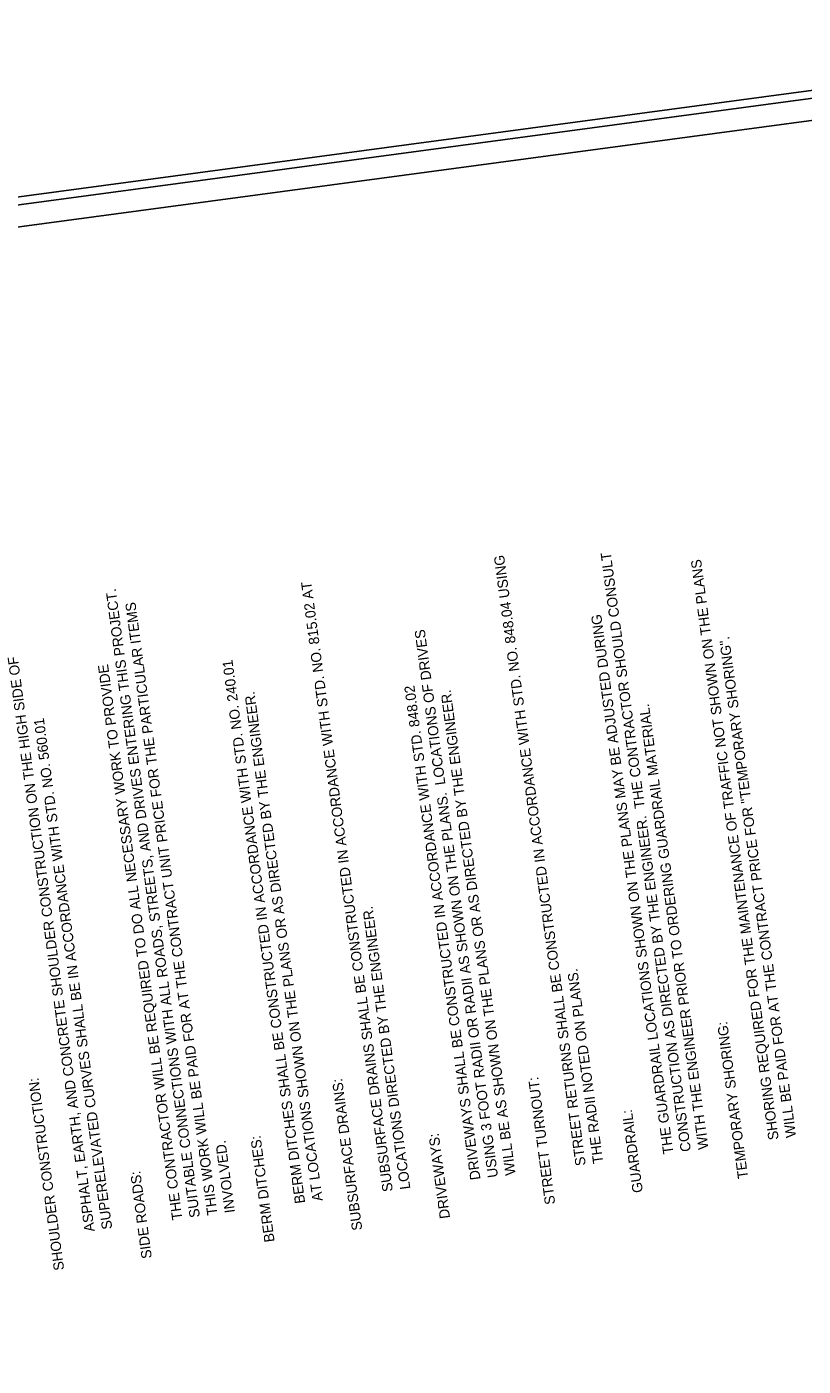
# Model space of a CAD drawing. Extents: x 2573931 to 2578852, y 980053 to 983667.
# Drawn here: x 2574414 to 2574945, y 982228 to 983142 of the extents above; entities that cross this region are included whole.
import ezdxf

# ---------------------------------------------------------------- set-up
doc = ezdxf.new("R2010")
doc.units = 0
for name, color, linetype in [('Sheet Border Standard 30in CELL', 7, 'Continuous'), ('Sheet Data Text CELL', 7, 'Continuous'), ('Sheet Plot Border Inside CELL', 7, 'Continuous'), ('Sheet Plot Border Outside CELL', 7, 'Continuous')]:
    doc.layers.add(name, color=color, linetype=linetype)

msp = doc.modelspace()

# ---------------------------------------------------------------- linework, layer by layer
at = {"layer": 'Sheet Border Standard 30in CELL'}
msp.add_lwpolyline([(2573998.57, 982950.72), (2574237.85, 981166.7), (2575486.67, 981334.19), (2575247.39, 983118.21)], close=True, dxfattribs=at)
at = {"layer": 'Sheet Plot Border Inside CELL'}
msp.add_lwpolyline([(2573993.55, 982965.18), (2574259.38, 980983.13), (2575514.27, 981151.44), (2575248.43, 983133.49)], close=True, dxfattribs=at)
at = {"layer": 'Sheet Plot Border Outside CELL'}
msp.add_lwpolyline([(2573966.13, 982966.95), (2574234.76, 980964.09), (2575543.04, 981139.56), (2575274.41, 983142.42)], close=True, dxfattribs=at)

# ---------------------------------------------------------------- texts
at = {"layer": 'Sheet Data Text CELL'}
for s, p in [('         STREET RETURNS SHALL BE CONSTRUCTED IN ACCORDANCE WITH STD. NO. 848.04 USING ', (2574799.57, 982341.9)), ('         CONSTRUCTION AS DIRECTED BY THE ENGINEER.  THE CONTRACTOR SHOULD CONSULT', (2574871.47, 982351.54)), ('         SHORING REQUIRED FOR THE MAINTENANCE OF TRAFFIC NOT SHOWN ON THE PLANS ', (2574931.39, 982359.58)), ('         SUBSURFACE DRAINS SHALL BE CONSTRUCTED IN ACCORDANCE WITH STD. NO. 815.02 AT ', (2574667.75, 982324.22)), ('         SUITABLE CONNECTIONS WITH ALL ROADS, STREETS, AND DRIVES ENTERING THIS PROJECT.  ', (2574535.93, 982306.54)), ('         THIS WORK WILL BE PAID FOR AT THE CONTRACT UNIT PRICE FOR THE PARTICULAR ITEMS ', (2574547.91, 982308.15)), ('         THE GUARDRAIL LOCATIONS SHOWN ON THE PLANS MAY BE ADJUSTED DURING ', (2574859.48, 982349.94)), ('         USING 3 FOOT RADII OR RADII AS SHOWN ON THE PLANS.  LOCATIONS OF DRIVES', (2574739.65, 982333.86)), ('         WILL BE PAID FOR AT THE CONTRACT PRICE FOR "TEMPORARY SHORING".', (2574943.37, 982361.19)), ('         ASPHALT, EARTH, AND CONCRETE SHOULDER CONSTRUCTION ON THE HIGH SIDE OF', (2574464.03, 982296.9)), ('         THE CONTRACTOR WILL BE REQUIRED TO DO ALL NECESSARY WORK TO PROVIDE ', (2574523.94, 982304.93)), ('         BERM DITCHES SHALL BE CONSTRUCTED IN ACCORDANCE WITH STD. NO. 240.01 ', (2574607.83, 982316.18)), ('         AT LOCATIONS SHOWN ON THE PLANS OR AS DIRECTED BY THE ENGINEER.  ', (2574619.81, 982317.79)), ('         DRIVEWAYS SHALL BE CONSTRUCTED IN ACCORDANCE WITH STD. 848.02', (2574727.66, 982332.26)), ('         WILL BE AS SHOWN ON THE PLANS OR AS DIRECTED BY THE ENGINEER.  ', (2574751.63, 982335.47)), ('         WITH THE ENGINEER PRIOR TO ORDERING GUARDRAIL MATERIAL.', (2574883.45, 982353.15)), ('         SUPERELEVATED CURVES SHALL BE IN ACCORDANCE WITH STD. NO. 560.01', (2574476.01, 982298.5)), ('         LOCATIONS DIRECTED BY THE ENGINEER.  ', (2574679.73, 982325.83)), ('         THE RADII NOTED ON PLANS.  ', (2574811.55, 982343.51)), ('TEMPORARY SHORING:  ', (2574907.42, 982356.36)), ('SHOULDER CONSTRUCTION:  ', (2574440.06, 982293.68)), ('SUBSURFACE DRAINS:', (2574643.78, 982321)), ('STREET TURNOUT:  ', (2574775.6, 982338.68)), ('GUARDRAIL:  ', (2574835.52, 982346.72)), ('DRIVEWAYS:  ', (2574703.7, 982329.04)), ('         INVOLVED.  ', (2574559.89, 982309.75)), ('BERM DITCHES:  ', (2574583.86, 982312.97)), ('SIDE ROADS:  ', (2574499.98, 982301.72))]:
    msp.add_text(s, height=7, rotation=97.63902, dxfattribs=at).set_placement(p)

doc.saveas('drawing.dxf')
